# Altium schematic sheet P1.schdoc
size 297 x 209 mm; Symbol: Drawing-Symbol_A4; Company: 嘉立创EDA; Version: V1.0; Page Size: A4; @Project Name: 电流电压转换; @Update Date: 2026-03-09; @Create Date: 2026-03-09; Device: Drawing-Symbol_A4; @Board Name: Board1; @Page Name: P1; @Create Time: 19:09:41; @Page Count: 1; @Page No: 1; @Schematic Name: Schematic1; @Update Time: 19:09:41; @Assembly Variant: Basic; Border: 1; Title Block Position: 3; Size: A4; Width: 1170; Height: 825; Region Start: 1; X Region Count: 6; Y Region Count: 4; Blade Width: 10; Title Block: 1
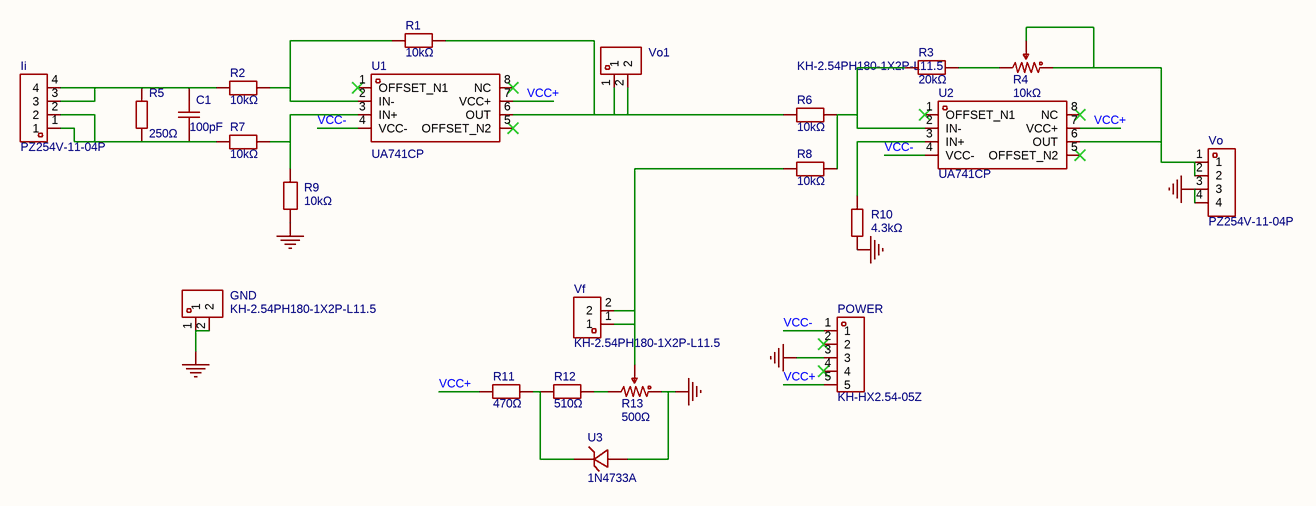
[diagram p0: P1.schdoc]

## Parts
C1  100pF  [CAP-TH_L5.5-W2.5-P5.00-D1.0]
GND  KH-2.54PH180-1X2P-L11.5  [HDR-TH_2P-P2.54-V-M]
Ii  PZ254V-11-04P  [HDR-TH_4P-P2.54-V-M]
POWER  KH-HX2.54-05Z  [CONN-TH_5P-P2.54_KH-HX2.54-05Z]
R1  10kΩ  [RES-TH_BD2.7-L6.2-P10.20-D0.4]
R2  10kΩ  [RES-TH_BD2.7-L6.2-P10.20-D0.4]
R3  20kΩ  [RES-TH_BD2.4-L6.3-P10.30-D0.6]
R4  10kΩ  [RES-ADJ-TH_3296W]
R5  250Ω  [RES-TH_BD2.2-L6.5-P10.50-D0.6]
R6  10kΩ  [RES-TH_BD2.7-L6.2-P10.20-D0.4]
R7  10kΩ  [RES-TH_BD2.7-L6.2-P10.20-D0.4]
R8  10kΩ  [RES-TH_BD2.7-L6.2-P10.20-D0.4]
R9  10kΩ  [RES-TH_BD2.7-L6.2-P10.20-D0.4]
R10  4.3kΩ  [RES-TH_BD2.4-L6.3-P10.30-D0.6]
R11  470Ω  [RES-TH_BD2.4-L6.3-P10.30-D0.6]
R12  510Ω  [RES-TH_BD2.4-L6.3-P10.30-D0.6]
R13  500Ω  [RES-ADJ-TH_3296W]
U1  UA741CP  [DIP-8_L9.6-W6.4-P2.54-LS7.6-BL-1]
U2  UA741CP  [DIP-8_L9.6-W6.4-P2.54-LS7.6-BL-1]
U3  1N4733A  [DO-41_BD2.4-L4.7-P8.70-D0.9-RD]
Vf  KH-2.54PH180-1X2P-L11.5  [HDR-TH_2P-P2.54-V-M]
Vo  PZ254V-11-04P  [HDR-TH_4P-P2.54-V-M]
Vo1  KH-2.54PH180-1X2P-L11.5  [HDR-TH_2P-P2.54-V-M]

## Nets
GND: GND.1 GND.2 POWER.3 R9.1 R10.1 R13.1 U3.2(A) Vo.3 Vo.4
VCC+: POWER.5 R11.1 U1.7(VCC+) U2.7(VCC+)
VCC-: POWER.1 U1.4(VCC-) U2.4(VCC-)
NetC1_1: C1.1 Ii.1 Ii.2 R5.1 R7.1
NetC1_2: C1.2 Ii.3 Ii.4 R2.1 R5.2
NetR1_1: R1.1 R2.2 U1.2(IN-)
NetR1_2: R1.2 R6.1 U1.6(OUT) Vo1.1 Vo1.2
NetR3_1: R3.1 R6.2 R8.2 U2.2(IN-)
NetR3_2: R3.2 R4.3
NetR4_1: R4.1 R4.2 U2.6(OUT) Vo.1 Vo.2
NetR7_2: R7.2 R9.2 U1.3(IN+)
NetR8_1: R8.1 R13.2 Vf.1 Vf.2
NetR10_2: R10.2 U2.3(IN+)
NetR11_2: R11.2 R12.1 U3.1(C)
NetR12_2: R12.2 R13.3

Not connected (* = marked no-connect by the designer): POWER 2* 4*; U1 1(OFFSET_N1)* 5(OFFSET_N2)* 8(NC)*; U2 1(OFFSET_N1)* 5(OFFSET_N2)* 8(NC)*

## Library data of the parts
C1 = N06B1B101KN0B0S0B0: 容值:100pF;精度:±10%;额定电压:1kV;温度系数:Y5P;; Manufacturer: STE(松田); AddInBom: yes; ModelId: 5444d7b7568c4408aeb251ff04ca2d910819f05c4eef4c71ace90d822a990e87; ModelName: CAP-TH_BD5.5-W2.5-P5.0; ModelTransform: 230.016,106.096,0,0,0,0,-0.005,0,-137.795; Tolerance: ±10%; Voltage Rating: 1kV; Pin Spacing: 5mm; Temperature Coefficient: Y5P; Body Thickness: 2.5mm
GND Vf Vo1 = KH-2.54PH180-1X2P-L11.5: 插针结构:1x2P;间距:2.54mm;行距:-;圆针/方针:方针;安装方式:直插;排数:单排;总PIN位数:2P;额定电流:3A;额定电压:-;配合针长度:6mm;塑高:2.5mm;端接针长度:3mm;触头材质:-;工作温度:-40℃~+105℃;颜色:黑色;; Manufacturer: kinghelm(金航标); AddInBom: yes; ModelId: e35305ec3aa84b66b849f914b715e73f0819f05c4eef4c71ace90d822a990e87; ModelName: HDR2.54-M-LI-1X2P; ModelTransform: 200,100,0,0,0,0,0,0,-118.11; Pin Structure: 1x2P; Pitch: 2.54mm; Circluar Pins/Square Pins: 方针; Current Rating: 3A
Ii Vo = PZ254V-11-04P: 插针结构:1x4P;间距:2.54mm;行距:-;圆针/方针:方针;安装方式:直插;排数:单排;总PIN位数:4P;额定电流:3A;额定电压:250V;配合针长度:6mm;塑高:2.5mm;端接针长度:3mm;触头材质:-;工作温度:-40℃~+105℃;颜色:黑色;; Manufacturer: XFCN(兴飞); Symbol: PZ254V-11-04P_C2691448; AddInBom: yes; ModelId: 112f4d05e8d64e99ab9a333894bea4f90819f05c4eef4c71ace90d822a990e87; ModelName: HDR-TH_4P-P2.54-M-LI-1X4P; ModelTransform: 399.999,104.7242,0,0,0,0,0,0,-118.11; Pin Structure: 1x4P; Pitch: 2.54mm; Circluar Pins/Square Pins: 方针; Current Rating: 3A; Voltage Rating (Max): 250V
POWER = KH-HX2.54-05Z: 插针结构:1x5P;间距:2.54mm;安装方式:直插;总PIN数:5P;排数:1;每排PIN数:5;额定电流:2.5A;触头材质:黄铜;触头镀层:锡;工作温度:-25℃~+85℃;; Manufacturer: kinghelm(金航标); AddInBom: yes; ModelId: e7bd94ca7e7e4016acf191f2280bdca80819f05c4eef4c71ace90d822a990e87; ModelTransform: 499.999,228.7397,0,0,0,0,0,-13.78,-133.858; Pins Structure: 1x5P; Pitch: 2.54mm; Number of PINs Per Row: 5; Current Rating: 2.5A; Voltage Rating: 250V; Plastic Material: PA66; Flame Retardant Rating: UL94V-0; Z-Height of the Board: 11.3mm; Y-Width of Bottom Edge on Board: 5.85mm
R1 R2 R7-R9 = MF1/4W-10K±1%-ST52: 电阻类型:金属膜电阻;阻值:10kΩ;精度:±1%;功率:250mW;温度系数:±100ppm/℃;; Manufacturer: VO(翔胜); AddInBom: yes; ModelId: f91fbe0e2e6f409498f09f811e4616fe0819f05c4eef4c71ace90d822a990e87; ModelTransform: 417.322,106.221,0,0,0,0,0,0,-196.85; Tolerance: ±1%; Voltage-Supply(Max): 250V; Power(Watts): 250mW
R3 = MFR-25FBF52-20K: 电阻类型:金属膜电阻;阻值:20kΩ;精度:±1%;功率:250mW;温度系数:±100ppm/℃;; Manufacturer: YAGEO(国巨); Add into BOM: yes; 3D Model: 463263665006444ab7a47bd11b0cf956; 3D Model Transform: 427.165,94.32816,0,0,0,0,0,0,-196.85; Tolerance: ±1%; Power(Watts): 250mW
R4 = 3296W-1-103_C48997937: 阻值:10kΩ;精度:±10%;功率:500mW;温度系数:±250ppm/℃;; Manufacturer: JIERR(捷而瑞); AddInBom: yes; ModelId: 3664f7b541aa4725a8b6d3b7a961f0780819f05c4eef4c71ace90d822a990e87; ModelTransform: 374.015,188.976,0,90,0,0,2.362,0.005,-137.795; Tolerance: ±10%; Power(Watts): 500mW; Number of Turns: 28
R5 = MFR0W4F2500A50: 电阻类型:金属膜电阻;阻值:250Ω;精度:±1%;功率:250mW;温度系数:±50ppm/℃;; Manufacturer: UNI-ROYAL(厚声); AddInBom: yes; ModelId: 259c3103781c424fb695c8049f0a17f30819f05c4eef4c71ace90d822a990e87; ModelTransform: 437.007,91.18383,0,0,0,0,0,0,-137.795; Tolerance: ±1%; Voltage-Supply(Max): 250V; Power(Watts): 250mW
R6 = MF1/4W-10K±1%-ST52: 电阻类型:金属膜电阻;阻值:10kΩ;精度:±1%;功率:250mW;温度系数:±100ppm/℃;; Manufacturer: VO(翔胜); 3D Model: f91fbe0e2e6f409498f09f811e4616fe0819f05c4eef4c71ace90d822a990e87; 3D Model Transform: 417.322,106.221,0,0,0,0,0,0,-196.85; Tolerance: ±1%; Voltage-Supply(Max): 250V; Power(Watts): 250mW; AddInBom: yes
R10 = MFR-25FBF52-4K3: 电阻类型:金属膜电阻;阻值:4.3kΩ;精度:±1%;功率:250mW;温度系数:±100ppm/℃;; Manufacturer: YAGEO(国巨); Add into BOM: yes; 3D Model: 463263665006444ab7a47bd11b0cf956; 3D Model Transform: 427.165,94.32816,0,0,0,0,0,0,-196.85; Tolerance: ±1%; Power(Watts): 250mW
R11 = MFR-25FTE52-470R: 电阻类型:金属膜电阻;阻值:470Ω;精度:±1%;功率:250mW;温度系数:±50ppm/℃;; Manufacturer: YAGEO(国巨); Symbol: RN 1/4W 5K1 F T/B A1; Add into BOM: yes; 3D Model: 463263665006444ab7a47bd11b0cf956; 3D Model Transform: 427.165,94.32816,0,0,0,0,0,0,-196.85; Tolerance: ±1%; Power(Watts): 250mW
R12 = RN 1/4W 510R F T/B A1: 电阻类型:金属膜电阻;阻值:510Ω;精度:±1%;功率:250mW;温度系数:±50ppm/℃;; Manufacturer: Tyohm(幸亚电阻); Add into BOM: yes; 3D Model: 463263665006444ab7a47bd11b0cf956; 3D Model Transform: 427.165,94.32816,0,0,0,0,0,0,-196.85; Tolerance: ±1%; Voltage-Supply(Max): 250V; Power(Watts): 250mW
R13 = 3296W-1-501LF: 阻值:500Ω;精度:±10%;功率:500mW;温度系数:±100ppm/℃;; Manufacturer: BOURNS; Symbol: 3296W-1-103_C48997937; 3D Model: 3664f7b541aa4725a8b6d3b7a961f0780819f05c4eef4c71ace90d822a990e87; 3D Model Transform: 374.015,188.976,0,90,0,0,2.362,0.005,-137.795; Tolerance: ±10%; Power(Watts): 500mW; Number of Turns: 25; Add into BOM: yes
U1 = UA741CP: 放大器数:单路;轨到轨:-;增益带宽积(GBP):-;输入失调电压(Vos):6mV;压摆率(SR):500V/ms;输入偏置电流(Ib):500nA;; Manufacturer: TI(德州仪器); AddInBom: yes; ModelId: 118a16105a4644d880cbe59ec0f5536f0819f05c4eef4c71ace90d822a990e87; ModelTransform: 377.952,309.842,0,0,0,0,0,0,-137.795; Number of Channels: 单路; Maximum Power Supply Range (Vdd-Vss): 36V; Vos - Input Offset Voltage: 6mV; Ib - Input Bias Current: 500nA; Input Offset Current(Ios): 200nA; Common Mode Rejection Ratio(CMRR): 90dB; Quiescent Current: 1.7mA; Output Current: 40mA; Single supply: -5V~15V; Dual Supply: -15V~15V
U2 = UA741CP: 放大器数:单路;轨到轨:-;增益带宽积(GBP):-;输入失调电压(Vos):6mV;压摆率(SR):500V/ms;输入偏置电流(Ib):500nA;; Manufacturer: TI(德州仪器); 3D Model: 118a16105a4644d880cbe59ec0f5536f0819f05c4eef4c71ace90d822a990e87; 3D Model Transform: 377.952,309.842,0,0,0,0,0,0,-137.795; Number of Channels: 单路; Maximum Power Supply Range (Vdd-Vss): 36V; Vos - Input Offset Voltage: 6mV; Ib - Input Bias Current: 500nA; Input Offset Current(Ios): 200nA; Common Mode Rejection Ratio(CMRR): 90dB; Quiescent Current: 1.7mA; Output Current: 40mA; Single supply: -5V~15V; Dual Supply: -15V~15V; AddInBom: yes
U3 = 1N4733A_C5157516: 二极管配置:独立式;稳压值(标称值):5.1V;稳压值(范围):4.85V~5.36V;耗散功率(Pd):1W;; Manufacturer: LGE(鲁光); AddInBom: yes; ModelId: 6de1e9b71a0d4751b4e9df530304c1a30819f05c4eef4c71ace90d822a990e87; ModelName: DO-41_D2.4-L4.7-P8.70; ModelTransform: 374.016,94.488,0,0,0,0,0,0,-137.795; Diode Configuration: 独立式; Zener Voltage(Nom): 5.1V; Reverse Leakage Current (Ir): 10uA@1.0V; Pd - Power Dissipation: 1W; Impedance(Zzt): 7Ω; Impedance(Zzk): 550Ω; Operating Junction Temperature Range: -65℃~+200℃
